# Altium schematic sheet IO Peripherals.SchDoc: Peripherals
size A4; DocumentNumber: 4; Revision: D.1(PCB.SCH); SheetNumber: 4; SheetTotal: 7
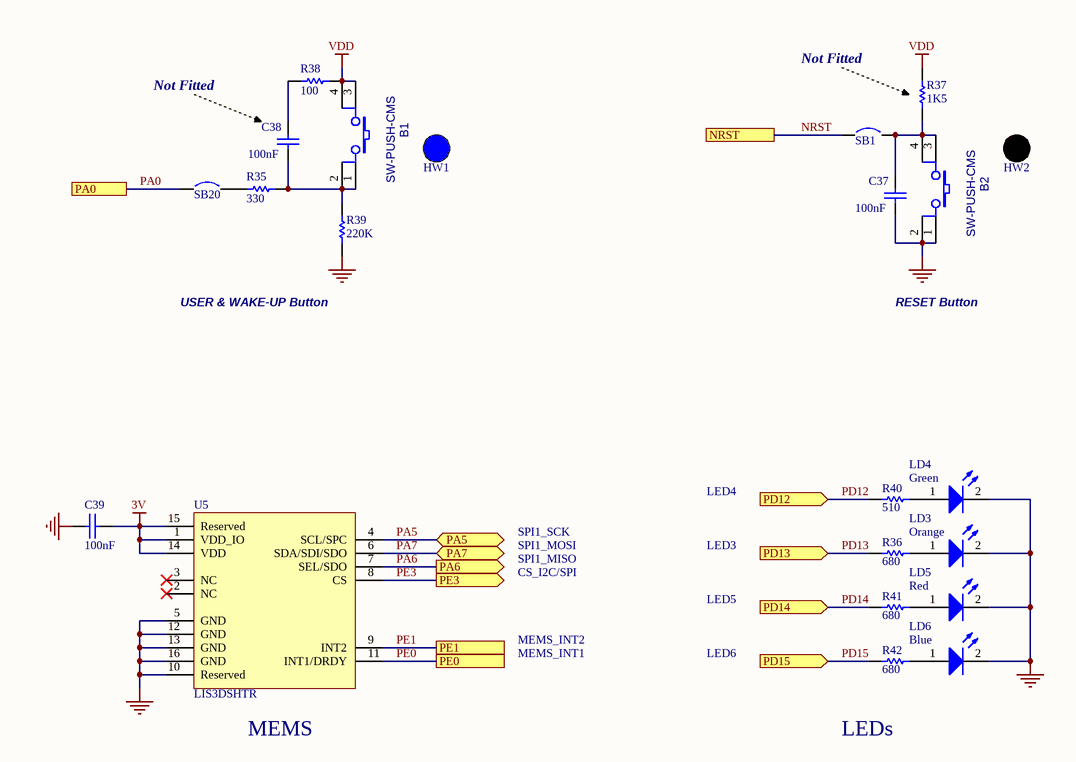
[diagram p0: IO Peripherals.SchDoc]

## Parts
B1  SW-PUSH-CMS  [SW4SMD]
B2  SW-PUSH-CMS  [SW4SMD]
C37  100nF  [0402C]
C38  100nF  [0402C]
C39  100nF  [0402C]
HW1  BUTTON_HAT_BLUE  (value not drawn)  (mechanical)
HW2  BUTTON_HAT_BLACK  (value not drawn)  (mechanical)
LD3  Orange  [LED0603]
LD4  Green  [LED0603]
LD5  Red  [LED0603]
LD6  Blue  [LED0603]
R35  330  [0603R]
R36  680  [0603R]
R37  1K5  [0402R]
R38  100  [0402R]
R39  220K  [0603R]
R40  510  [0603R]
R41  680  [0603R]
R42  680  [0603R]
SB1  Circuit Breaker  [JUMPER]  (value not drawn)
SB20  Circuit Breaker  [JUMPER]  (value not drawn)
U5  LIS3DSHTR  [LGA16_]

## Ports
NRST, PA0, PA5 (bidir), PA6 (out), PA7 (bidir), PD12 (in), PD13 (in), PD14 (in), PD15 (in), PE0, PE1, PE3 (out)

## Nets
3V: C39.2 U5.1(VDD_IO) U5.14(VDD) U5.15(Reserved)
GND: B2.1 B2.2 C37.1 C39.1 LD3.2(K) LD4.2(K) LD5.2(K) LD6.2(K) R39.1 U5.5(GND) U5.10(Reserved) U5.12(GND) U5.13(GND) U5.16(GND)
VDD: B1.3 B1.4 R37.2 R38.2
NRST: SB1.1 ; port NRST
PA0: SB20.1 ; port PA0
PA5: U5.4(SCL/SPC) ; port PA5
PA6: U5.7(SEL/SDO) ; port PA6
PA7: U5.6(SDA/SDI/SDO) ; port PA7
PD12: R40.2 ; port PD12
PD13: R36.2 ; port PD13
PD14: R41.2 ; port PD14
PD15: R42.2 ; port PD15
PE0: U5.11(INT1/DRDY) ; port PE0
PE1: U5.9(INT2) ; port PE1
PE3: U5.8(CS) ; port PE3
NetB1_1: B1.1 B1.2 C38.1 R35.2 R39.2
NetB2_3: B2.3 B2.4 C37.2 R37.1 SB1.2
NetC38_2: C38.2 R38.1
NetLD3_1: LD3.1(A) R36.1
NetLD4_1: LD4.1(A) R40.1
NetLD5_1: LD5.1(A) R41.1
NetLD6_1: LD6.1(A) R42.1
NetR35_1: R35.1 SB20.2

Not connected (* = marked no-connect by the designer): U5 2(NC)* 3(NC)*

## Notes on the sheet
- Not Fitted
- USER & WAKE-UP Button
- RESET Button
- LED4
- SPI1_MOSI
- SPI1_SCK
- SPI1_MISO
- CS_I2C/SPI
- LED3
- MEMS_INT2
- LED5
- MEMS_INT1
- LED6
- (near U5) MEMS
- LEDs

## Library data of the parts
B1 = SW-PUSH-CMS_NEW: Non-Open Push-Button 0.1A 24V; Manuf_1: CHAU-HUA; Manuf_Part_1: CTSM-644B-V-T/R; cap_dec: ---
B2 = SW-PUSH-CMS_NEW: Non-Open Push-Button 0.1A 24V; Manuf_1: CHAU-HUA; Manuf_Part_1: CTSM-644N-V-T/R; cap_dec: ---
C37 C39 = CAP: Capacitor; Manuf_Part_1: CC0402KRX7R7BB104; Manuf_1: YAGEO
C38 = CAP: Capacitor; Fitted: NO
HW1 = BUTTON_HAT_BLUE: switch hat,blue; Manuf_Part_1: KTSC-62B; Manuf_1: CHAU-HUA
HW2 = BUTTON_HAT_BLACK: switch hat,black; Manuf_1: CHAU-HUA; Manuf_Part_1: KTSC-62K
LD3 = LED2: Typical RED, GREEN, YELLOW, AMBER GaAs LED; Manuf_Part_1: 19-217/S2C-AM2N2VY/3T; Manuf_1: EVERLIGHT
LD4 = LED2: Typical RED, GREEN, YELLOW, AMBER GaAs LED; Manuf_1: EVERLIGHT; Manuf_Part_1: 19-213SYGC/S530-E2/TR8
LD5 = LED2: Typical RED, GREEN, YELLOW, AMBER GaAs LED; Manuf_Part_1: 19-213-R6C-AP1Q2B-3T; Manuf_1: EVERLIGHT
LD6 = LED2: Typical RED, GREEN, YELLOW, AMBER GaAs LED; Manuf_1: EVERLIGHT; Manuf_Part_1: 19-217/BHC-ZL1M2RY/3T
R35 = res1: Resistor; Manuf_Part_1: RC0603FR-07330RL; Manuf_1: YAGEO
R36 R41 R42 = Res1: Resistor; Manuf_Part_1: RC0603FR-07680RL; Manuf_1: YAGEO
R37 = res1: Resistor; Manuf_Part_1: RC0402FR-071K5L; Manuf_1: YAGEO; Fitted: NO
R38 = res1: Resistor; Manuf_Part_1: RC0402FR-07100RL; Manuf_1: YAGEO
R39 = res1: Resistor; Manuf_Part_1: RC0603FR-07220KL; Manuf_1: YAGEO
R40 = Res1: Resistor; Manuf_Part_1: RC0603FR-07510RL; Manuf_1: YAGEO
SB1 SB20 = Circuit Breaker: Solder: YES
U5 = LIS3DSH_: MEMS motion sensor 3-axis - ±2g/±4g/±6g/±8g/±16g digital output accelerometer; Manuf_1: STM; Provided: ST; ref St: to be created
